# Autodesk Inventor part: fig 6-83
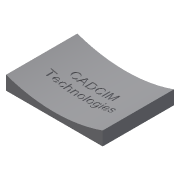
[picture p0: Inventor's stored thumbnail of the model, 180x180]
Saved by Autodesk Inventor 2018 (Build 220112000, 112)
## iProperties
Shininess: 64.0
Length Units: 11269
Angle Units: 11279
Time Units: 11290
Mass Units: 11283
Length Display Precision: 3
Angle Display Precision: 2
Compacted: True
Part Number: fig 6-83
Document SubType Name: Modeling
Created: 2002-12
Designer: deepak
Density: 1 g/cm^3
Material: Generic
Appearance: Default
Density: 0.0
Volumn: 0.0
Area: 0.0
PropertySet Name: Model Information
Control State: 0
Master: False
Checked Out: False
Author: deepak
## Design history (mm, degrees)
sketch "Sketch1"
  geometry: L1 (-39.922, 33.786)-(30.103, 33.786); L2 (30.103, 33.786)-(30.103, -17.894); L3 (30.103, -17.894)-(-39.922, -17.894); L4 (-39.922, -17.894)-(-39.922, 33.786)
  constraints: 8 end point, 2 parallel, 1 horizontal, 1 perpendicular
extrude "Extrusion1" new body sketch "Sketch1" distance "d0" = 10; taper "d1" = 0 deg
workplane "Work Plane1"
sketch "Sketch2"
  geometry: L1 (-37.656, 15.034)-(26.28, 15.034); L2 (26.28, 15.034)-(26.28, 10.168); L3 (26.28, 10.168)-(-37.656, 10.168); L4 (-37.656, 10.168)-(-37.656, 15.034)
  constraints: 2 other
sketch "Sketch3"
  geometry: L1 (70.026, 10)-(0, 10) reference; A1 r 105 centre (35.013, 108.99) between (0, 10) and (70.026, 10)
  constraints: 2 point on circle, 1 centre point
  dimensions: "d5" = 105 radius of A1
extrude "Extrusion2" cut sketch "Sketch3" extent not by distance; stored distance "d3" = 10; taper "d4" = 0 deg
emboss "Emboss4" sketch "Sketch2" dims "d14" = 1, "d15" = 0
body "Solid1"
other parameters: "d2" = 5
